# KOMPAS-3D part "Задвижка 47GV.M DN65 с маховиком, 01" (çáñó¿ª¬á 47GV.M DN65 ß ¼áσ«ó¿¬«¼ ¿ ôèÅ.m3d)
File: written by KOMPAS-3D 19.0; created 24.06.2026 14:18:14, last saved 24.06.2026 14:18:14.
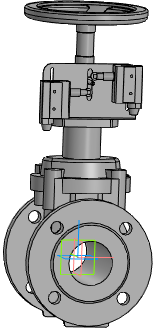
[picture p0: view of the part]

Document properties: Автор: Евгений; Полное имя файла: Z:\3.Личные\sachek\Dendor\3D для проектировщиков\2.7 Тип 47GV.M Задвижка клиновая фланцевая с обрезиненным клином\47GV.M DN65\Задвижка 47GV.M DN65 с маховиком.a3d

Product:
- Part/product: Задвижка 47GV.M DN65 с маховиком  | designation 01
    Масса: 10.055
  - Component [detail]: Корпус  | designation DR.47GVM.065.16.00.001  | pos. 3  | Материал: ВЧ50 ГОСТ 7293-85 (density 7200 kg/m3); Масса: 11.3996; Раздел спецификации: Детали; Форматы листов документа: 2xA3; source file: ..\47GV.M DN65\DR.47GVM.050.16.00.001 - Корпус.cdw, ..\47GV.M DN65\Корпус DN65.m3d
  - Component [assembly]: Клин с направляющими  | designation DR.47GVM.050.16.01.000  | pos. 4  | Раздел спецификации: Сборочные единицы; Форматы листов документа: A4; source file: ..\47GV.M DN65\DR.47GVM.050.16.01.000  - Клин с направляющими.a3d, ..\47GV.M DN65\DR.47GVM.050.16.01.000  - Клин с направляющими.spw, ..\47GV.M DN65\DR.47GVM.050.16.01.000  СБ - Клин с направляющими.cdw
  - Component [detail]: Крышка DN65  | pos. 4  | Материал: ВЧ50 ГОСТ 7293-85 (density 7200 kg/m3); Масса: 3.48496; Раздел спецификации: Детали; Форматы листов документа: 2xA3; source file: ..\47GV.M DN65\DR.47GVM.050.16.00.002 - Крышка.cdw, ..\47GV.M DN65\DR.47GVM.065.16.00.002 - Крышка.cdw, ..\47GV.M DN65\Крышка DN65.m3d
  - Component [detail]: Шпиндель  | pos. 5  | Материал: Сталь 20Х13 ГОСТ 5632-2014 (density 7670 kg/m3); Масса: 0.101759; Раздел спецификации: Детали; source file: ..\47GV.M DN50\DR.47GVM.050.16.00.003 - Шпиндель.cdw, ..\47GV.M DN50\Шпиндель 47GV.M DN50.m3d, ..\47GV.M DN65\DR.47GVM.050.16.00.003 - Шпиндель.cdw
  - Component [detail]: Маховик 180  | pos. 20  | Масса: 0.340724; Раздел спецификации: Прочие изделия; source file: ..\47GV.M DN50\Маховик 160.m3d
  - Component [standard]: Шайба821695878  | pos. 16
      Материал: Сталь 12Х18Н10Т ГОСТ 5632-2014 (density 1000 kg/m3)
      Масса: 0.000793943
      Раздел спецификации: Стандартные изделия
      Примечание: См. п.6 ТТ
      Рассекать на разрезах: no
      additional columns: ГОСТ 6958-78; A 8.21
  - Component [standard]: Болт86g187798  | pos. 17  | Масса: 0.0123; Раздел спецификации: Стандартные изделия; Примечание: См. п.6 ТТ; Рассекать на разрезах: no; additional columns: ГОСТ 7798-70; М8-6gx18
  - Component: Насадка для УКП  | designation DR.47GVM.UKP.050.16.00.001  | Материал: Сталь 08Х18Н10 ГОСТ 5632-2014 (density 7900 kg/m3); Масса: 0.411057; Раздел спецификации: Детали; Форматы листов документа: A4; source file: ..\47GV.M DN50\DR.47GVM.UKP.050.16.00.001 - Насадка для УКП.cdw, ..\47GV.M DN50\DR.47GVM.UKP.050.16.00.001 Насадка для УКП.m3d, ..\47GV.M DN50\DR.47GVM.UKP.100.16.00.001 - Насадка для УКП.cdw
  - Component: Кронштейн  | designation DR.47GVM.UKP.050.16.00.002  | Материал: Ст3сп ГОСТ 380-2005 (density 7850 kg/m3); Масса: 0.148202; Раздел спецификации: Детали; Форматы листов документа: A3; source file: ..\47GV.M DN50\DR.47GVM.UKP.050.16.00.002 - Кронштейн.cdw, ..\47GV.M DN50\DR.47GVM.UKP.050.16.00.002 - Кронштейн.m3d, ..\47GV.M DN50\DR.47GVM.UKP.100.16.00.002 - Кронштейн.cdw
  - Component: Контргайка  | designation DR.47GVM.UKP.050.16.00.003  | Материал: Сталь 08Х18Н10 ГОСТ 5632-2014 (density 7900 kg/m3); Масса: 0.0897966; Раздел спецификации: Детали; Форматы листов документа: A4; source file: ..\47GV.M DN50\DR.47GVM.UKP.050.16.00.003 - Контргайка.cdw, ..\47GV.M DN50\DR.47GVM.UKP.050.16.00.003 - Контргайка.m3d, ..\47GV.M DN50\DR.47GVM.UKP.100.16.00.003 - Контргайка.cdw
  - Component: Винт установочный М6х45  | designation DR.47GVM.UKP.050.16.00.005  | Материал: Сталь 08Х18Н10 ГОСТ 5632-2014 (density 7900 kg/m3); Масса: 0.00994284; source file: ..\47GV.M DN50\DR.47GVM.UKP.050.16.00.005 Винт установочный.m3d
  - Component: Концевик AZ7311  | qty 2  | Масса: 0.377378; source file: ..\47GV.M DN50\Концевик AZ7311.m3d
- Part/product: Задвижка 47GV.M DN65 с маховиком
    Масса: 17.0049
    Раздел спецификации: Документация
    Форматы листов документа: 2xA3
    source file: ..\47GV.M DN65\DR.47GVM.050.16.00.000 - Задвижка с обрезиненным клином DN50.spw, ..\47GV.M DN65\DR.47GVM.050.16.00.000 СБ - Задвижка с обрезиненным клином DN100.cdw
  - Component: Задвижка с обрезиненным клином DN50. Сборочный чертеж  | designation DR.47GVM.050.16.00.000СБ  | pos. 0  | Масса: 10.0548; Раздел спецификации: Документация; Форматы листов документа: 2xA3; source file: ..\47GV.M DN65\DR.47GVM.050.16.00.000 СБ - Задвижка с обрезиненным клином DN100.cdw

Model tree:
1. Операция без истории:1

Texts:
  Точка начала. Х
  Точка начала. Y
  Точка начала. Z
